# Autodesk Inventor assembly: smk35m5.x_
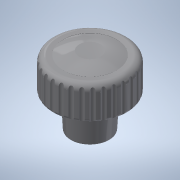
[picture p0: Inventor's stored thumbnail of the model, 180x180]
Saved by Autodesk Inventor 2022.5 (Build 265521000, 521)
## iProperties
Part Number: smk35m5.x_
Material: 一般
Document SubType Name: Assembly
Designer: ImaoCorp
Sending System: SOLIDWORKS 2017-2017317
MC: AMD64
MC_MODEL: Intel64 Family 6 Model 60 Stepping 3, GenuineIntel
OS: Windows_NT
FRU: Parasolid Version 29.0, build 201,  4-17-2017
FORMAT: text
GUISE: transmit
KEY: smk35m5
FILE: smk35m5.x_t
DATE: Wed Sep 18 16:12:41 2019
Author: ImaoCorp
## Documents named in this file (3)
- X:\14_SW2022-Inv2022\00_全2023-1023新製品(TCC)まで\s\smk35m5\SMK35M5.iam
- X:\14_SW2022-Inv2022\00_全2023-1023新製品(TCC)まで\s\smk35m5\smk35m5_01.ipt
- X:\14_SW2022-Inv2022\00_全2023-1023新製品(TCC)まで\s\smk35m5\smk35m5_02.ipt
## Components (2 placed, 2 different names)
1. smk35m5_01
2. smk35m5_02
